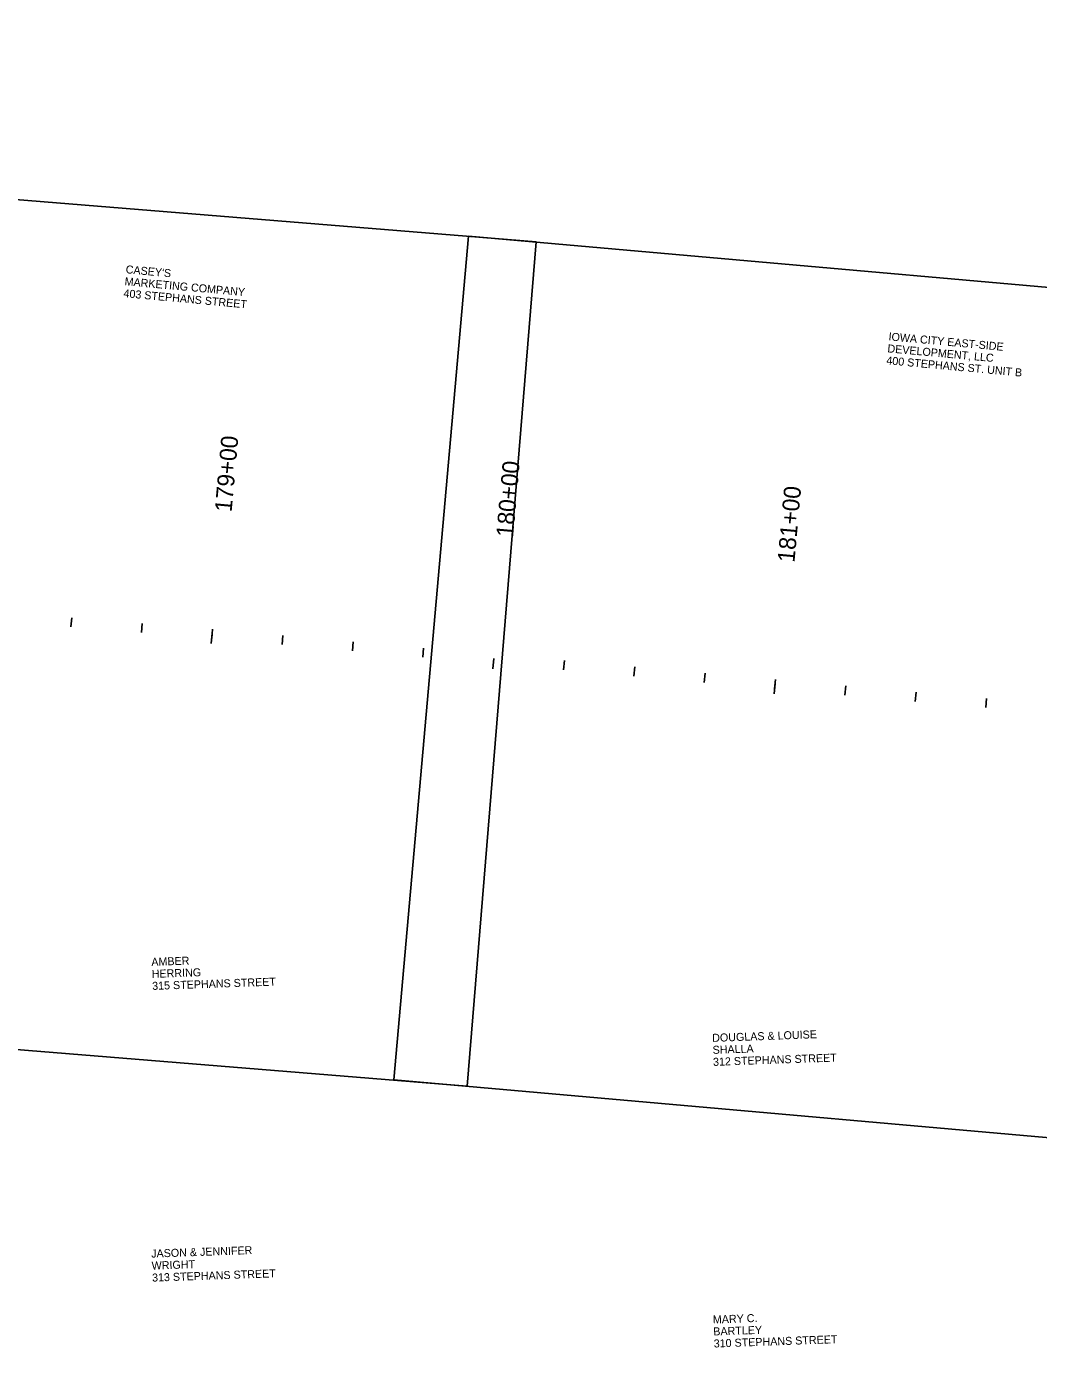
# Model space of a CAD drawing. Extents: x 20499788 to 20505371, y 7953467 to 7954209.
# Drawn here: x 20501543.6 to 20501901.8, y 7953657.4 to 7954125.3 of the extents above; entities that cross this region are included whole.
import ezdxf

# ---------------------------------------------------------------- set-up
doc = ezdxf.new("R2010")
doc.units = 0
for name, color, linetype in [('NamedBoundary', 7, 'Continuous'), ('Text', 7, 'Continuous'), ('TextAlignmentLrg', 7, 'Continuous'), ('TextAlignmentSml', 7, 'Continuous')]:
    doc.layers.add(name, color=color, linetype=linetype)

msp = doc.modelspace()

# ---------------------------------------------------------------- linework, layer by layer
at = {"layer": 'NamedBoundary'}
for points in [[(20500786.55, 7954125.26), (20500762.22, 7953826.25), (20501699.61, 7953749.96), (20501723.94, 7954048.98)], [(20501700.08, 7954051), (20501673.66, 7953752.17), (20502610.5, 7953669.34), (20502636.92, 7953968.17)]]:
    msp.add_lwpolyline(points, close=True, dxfattribs=at)
at = {"layer": 'TextAlignmentLrg'}
for p, q in [((20501609.18, 7953908.55), (20501609.47, 7953911.82)), ((20501708.95, 7953901.47), (20501708.62, 7953897.81)), ((20501808.38, 7953890.72), (20501808.68, 7953893.98))]:
    msp.add_line(p, q, dxfattribs=at)
at = {"layer": 'TextAlignmentSml'}
for p, q in [((20501559.34, 7953912.59), (20501559.6, 7953915.85)), ((20501584.26, 7953910.61), (20501584.52, 7953913.87)), ((20501609.34, 7953910.38), (20501609.02, 7953906.73)), ((20501634.08, 7953906.33), (20501634.37, 7953909.59)), ((20501658.98, 7953904.1), (20501659.27, 7953907.36)), ((20501683.88, 7953901.87), (20501684.17, 7953905.13)), ((20501708.95, 7953901.47), (20501708.62, 7953897.81)), ((20501733.68, 7953897.41), (20501733.97, 7953900.67)), ((20501758.58, 7953895.18), (20501758.87, 7953898.44)), ((20501783.48, 7953892.95), (20501783.77, 7953896.21)), ((20501808.55, 7953892.55), (20501808.22, 7953888.89)), ((20501833.28, 7953888.49), (20501833.58, 7953891.75)), ((20501858.18, 7953886.26), (20501858.48, 7953889.52)), ((20501883.08, 7953884.03), (20501883.38, 7953887.29))]:
    msp.add_line(p, q, dxfattribs=at)

# ---------------------------------------------------------------- texts
at = {"layer": 'Text'}
for s, height, rotation, p in [("CASEY'S", 2.835, 354.7645, (20501578.63, 7954037.87)), ('MARKETING COMPANY', 2.8346, 354.7645, (20501578.24, 7954033.64)), ('403 STEPHANS STREET', 2.8346, 354.7645, (20501577.85, 7954029.41)), ('IOWA CITY EAST-SIDE', 2.8346, 354.7645, (20501848.61, 7954014.1)), ('DEVELOPMENT, LLC', 2.8346, 354.7645, (20501848.22, 7954009.87)), ('400 STEPHANS ST. UNIT B', 2.8346, 354.7645, (20501847.83, 7954005.63)), ('AMBER', 2.835, 2.0248, (20501587.83, 7953792.56)), ('HERRING', 2.835, 2.0248, (20501587.98, 7953788.31)), ('315 STEPHANS STREET', 2.8346, 2.0248, (20501588.13, 7953784.06)), ('DOUGLAS & LOUISE', 2.8346, 2.0248, (20501786.33, 7953765.66)), ('SHALLA', 2.835, 2.0248, (20501786.48, 7953761.41)), ('312 STEPHANS STREET', 2.8346, 2.0248, (20501786.63, 7953757.16)), ('JASON & JENNIFER', 2.8346, 2.0248, (20501587.79, 7953689.26)), ('WRIGHT', 2.835, 2.0248, (20501587.94, 7953685.01)), ('313 STEPHANS STREET', 2.8346, 2.0248, (20501588.09, 7953680.76)), ('MARY C.', 2.835, 2.0248, (20501786.57, 7953665.93)), ('BARTLEY', 2.835, 2.0248, (20501786.72, 7953661.68)), ('310 STEPHANS STREET', 2.8346, 2.0248, (20501786.87, 7953657.43))]:
    msp.add_text(s, height=height, rotation=rotation, dxfattribs=at).set_placement(p)
at = {"layer": 'TextAlignmentLrg'}
msp.add_text('180+00', height=6.012, rotation=84.8834, dxfattribs=at).set_placement((20501715.79, 7953944.19))
at = {"layer": 'TextAlignmentSml'}
for s, p in [('179+00', (20501616.19, 7953953.11)), ('180+00', (20501715.79, 7953944.19)), ('181+00', (20501815.39, 7953935.27))]:
    msp.add_text(s, height=6.012, rotation=84.8834, dxfattribs=at).set_placement(p)

doc.saveas('drawing.dxf')
